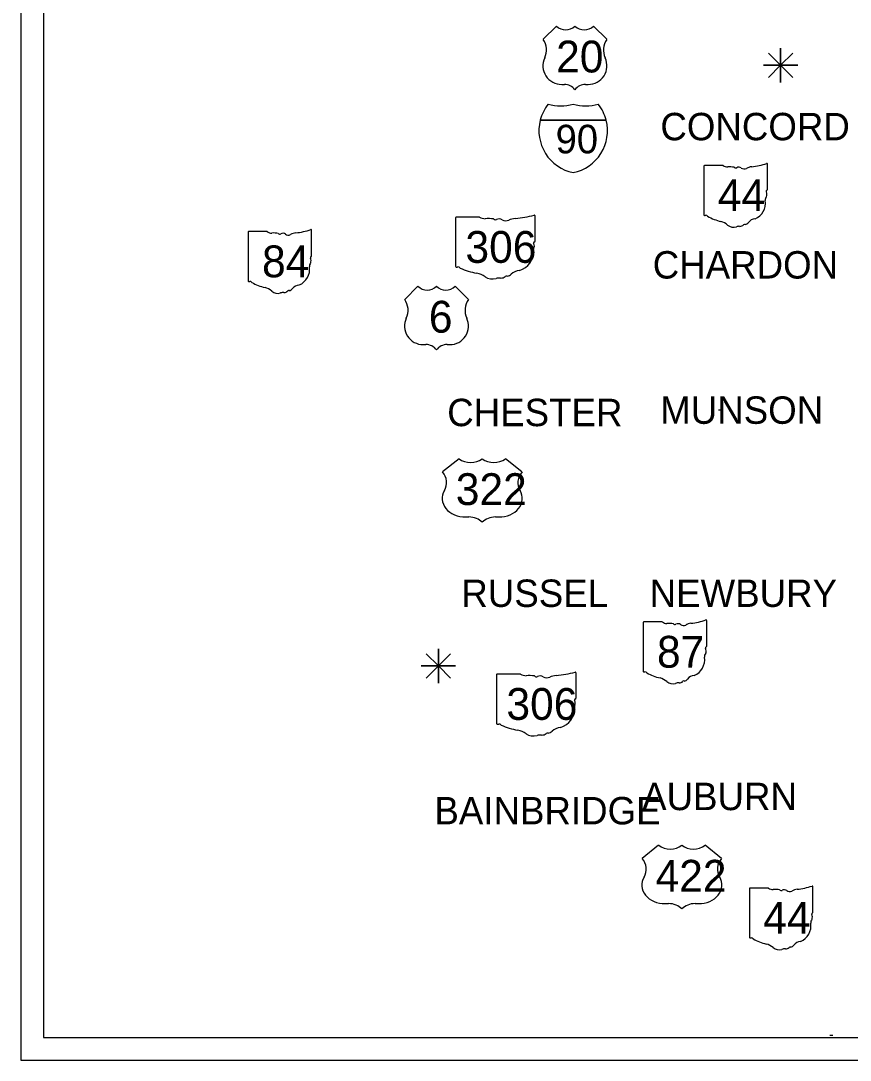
# Model space of a CAD drawing. Extents: x -1 to 48.3, y -9.3 to 22.
# Drawn here: x 2 to 5.63, y 14 to 18.55 of the extents above; entities that cross this region are included whole.
import ezdxf

# ---------------------------------------------------------------- set-up
doc = ezdxf.new("R2010")
doc.units = 0
for name, color, linetype in [('Default', 7, 'Continuous'), ('GM_X_County', 7, 'Continuous'), ('GM_X_County_Road', 7, 'Continuous'), ('GM_X_Minor_Lake_Text', 7, 'Continuous'), ('GM_X_Minor_River_Text', 7, 'Continuous'), ('GM_X_Township', 7, 'Continuous')]:
    doc.layers.add(name, color=color, linetype=linetype)

msp = doc.modelspace()

# ---------------------------------------------------------------- linework, layer by layer
at = {"layer": 'Default'}
for p, q in [((5.0538, 16.8468), (5.0668, 16.8468)), ((5.5402, 14.1091), (5.5532, 14.1091))]:
    msp.add_line(p, q, dxfattribs=at)
at = {"layer": 'GM_X_County'}
for p, q in [((2, 21), (2, 14)), ((2.1, 20.9), (2.1, 14.1)), ((2.1, 14.1), (8.9, 14.1)), ((2, 14), (9, 14))]:
    msp.add_line(p, q, dxfattribs=at)
at = {"layer": 'GM_X_County_Road'}
for p, q in [((4.9894, 17.913), (4.9894, 17.7017)), ((5.0737, 17.9167), (4.9921, 17.9167)), ((5.2678, 17.8114), (5.2678, 17.9219)), ((5.2678, 17.8114), (5.2678, 17.8114)), ((3.9026, 17.6867), (3.9026, 17.4754)), ((4.0079, 17.6903), (3.906, 17.6903)), ((4.2506, 17.585), (4.2506, 17.6956)), ((2.9944, 17.6237), (2.9944, 17.4123)), ((3.0787, 17.6273), (2.9971, 17.6273)), ((3.2728, 17.522), (3.2728, 17.6325)), ((4.2506, 17.5851), (4.2506, 17.585)), ((3.2728, 17.522), (3.2728, 17.522)), ((4.7233, 15.9147), (4.7233, 15.7033)), ((4.8076, 15.9183), (4.7261, 15.9183)), ((5.0018, 15.813), (5.0018, 15.9235)), ((5.0017, 15.813), (5.0018, 15.813)), ((4.0818, 15.6862), (4.0818, 15.4749)), ((4.1872, 15.6898), (4.0853, 15.6898)), ((4.4299, 15.5845), (4.4299, 15.6951)), ((4.4298, 15.5845), (4.4299, 15.5845)), ((5.1885, 14.7501), (5.1885, 14.5388)), ((5.2728, 14.7537), (5.1912, 14.7537)), ((5.4669, 14.6484), (5.4669, 14.759)), ((5.4669, 14.6484), (5.4669, 14.6484))]:
    msp.add_line(p, q, dxfattribs=at)
for centre, radius, start, end in [((4.9926, 17.9135), 0.00323, 98.1301, 188.1301), ((5.0931, 17.9412), 0.0313, 231.6195, 271.1119), ((5.1035, 17.798), 0.1123, 80.4867, 94.9883), ((5.129, 17.9146), 0.00903, 219.7921, 297.1024), ((5.1422, 17.8902), 0.0188, 54.4667, 119.1411), ((5.1664, 17.9237), 0.0226, 233.8562, 294.8282), ((5.2063, 17.8521), 0.0594, 97.3462, 120.7689), ((5.1687, 18.2048), 0.2953, 275.8445, 288.9065), ((5.2647, 17.9224), 0.0031, 351.8621, 97.738), ((5.2671, 17.8033), 0.0048, 107.944, 210.337), ((5.2366, 17.7893), 0.0288, 340.033, 23.6496), ((5.2645, 17.8109), 0.00332, 289.6038, 7.7341), ((5.1852, 17.751), 0.0739, 292.3089, 8.9858), ((5.2789, 17.7651), 0.021, 136.8065, 186.9296), ((4.9926, 17.7013), 0.00325, 171.9584, 258.3066), ((4.9931, 17.7229), 0.0248, 267.339, 280.6039), ((4.9982, 17.6895), 0.00895, 29.7484, 93.2717), ((5.1112, 17.8794), 0.2132, 240.4129, 257.1985), ((5.0477, 17.6068), 0.0667, 47.1842, 75.836), ((5.1198, 17.6885), 0.0423, 230.7004, 286.2918), ((5.1474, 17.6727), 0.0226, 268.777, 315.5493), ((5.1678, 17.6522), 0.00635, 65.7517, 132.6484), ((5.1651, 17.6812), 0.0239, 282.8732, 323.2771), ((5.2163, 17.6424), 0.0404, 94.4031, 142.5768), ((2.9976, 17.6241), 0.00323, 98.1301, 188.1301), ((3.0981, 17.6518), 0.0313, 231.6195, 271.1119), ((3.1085, 17.5087), 0.1123, 80.4867, 94.9883), ((3.134, 17.6252), 0.00903, 219.7921, 297.1024), ((3.1472, 17.6008), 0.0188, 54.4667, 119.1411), ((3.1714, 17.6343), 0.0226, 233.8562, 294.8282), ((3.2113, 17.5627), 0.0594, 97.3462, 120.7689), ((3.1737, 17.9154), 0.2953, 275.8445, 288.9065), ((3.2697, 17.633), 0.0031, 351.8621, 97.738), ((5.1443, 17.6154), 0.0348, 85.6951, 111.2099), ((3.2721, 17.5139), 0.0048, 107.944, 210.337), ((3.2695, 17.5216), 0.00332, 289.6038, 7.7341), ((3.1902, 17.4617), 0.0739, 292.3089, 8.9858), ((3.2839, 17.4757), 0.021, 136.8065, 186.9296), ((3.2416, 17.4999), 0.0288, 340.033, 23.6496), ((2.9976, 17.4119), 0.00325, 171.9584, 258.3066), ((2.9981, 17.4335), 0.0248, 267.339, 280.6039), ((3.0032, 17.4001), 0.00895, 29.7484, 93.2717), ((3.1163, 17.59), 0.2132, 240.4129, 257.1985), ((3.0527, 17.3174), 0.0667, 47.1842, 75.836), ((3.2213, 17.353), 0.0404, 94.4031, 142.5768), ((3.1248, 17.3991), 0.0423, 230.7004, 286.2918), ((3.1493, 17.326), 0.0348, 85.6951, 111.2099), ((3.1524, 17.3833), 0.0226, 268.777, 315.5493), ((3.1728, 17.3628), 0.00635, 65.7517, 132.6484), ((3.1701, 17.3918), 0.0239, 282.8732, 323.2771), ((4.9026, 16.2064), 0.2953, 275.8445, 288.9065), ((4.9987, 15.924), 0.0031, 351.8621, 97.738), ((4.7265, 15.9151), 0.00323, 98.1301, 188.1301), ((4.827, 15.9428), 0.0313, 231.6195, 271.1119), ((4.8374, 15.7996), 0.1123, 80.4867, 94.9883), ((4.8629, 15.9162), 0.00903, 219.7921, 297.1024), ((4.8762, 15.8918), 0.0188, 54.4667, 119.1411), ((4.9004, 15.9253), 0.0226, 233.8562, 294.8282), ((4.9402, 15.8537), 0.0594, 97.3462, 120.7689), ((5.001, 15.8049), 0.0048, 107.944, 210.337), ((4.9705, 15.7909), 0.0288, 340.033, 23.6496), ((4.9985, 15.8125), 0.00332, 289.6038, 7.7341), ((4.9191, 15.7527), 0.0739, 292.3089, 8.9858), ((5.0129, 15.7667), 0.021, 136.8065, 186.9296), ((4.7265, 15.7029), 0.00325, 171.9584, 258.3066), ((4.727, 15.7245), 0.0248, 267.339, 280.6039), ((4.7321, 15.6911), 0.00895, 29.7484, 93.2717), ((4.8452, 15.881), 0.2132, 240.4129, 257.1985), ((4.7816, 15.6084), 0.0667, 47.1842, 75.836), ((4.8538, 15.6901), 0.0423, 230.7004, 286.2918), ((4.8782, 15.617), 0.0348, 85.6951, 111.2099), ((4.8813, 15.6743), 0.0226, 268.777, 315.5493), ((4.9017, 15.6538), 0.00635, 65.7517, 132.6484), ((4.899, 15.6828), 0.0239, 282.8732, 323.2771), ((4.9503, 15.644), 0.0404, 94.4031, 142.5768), ((5.1917, 14.7505), 0.00323, 98.1301, 188.1301), ((5.2922, 14.7783), 0.0313, 231.6195, 271.1119), ((5.3026, 14.6351), 0.1123, 80.4867, 94.9883), ((5.3281, 14.7516), 0.00903, 219.7921, 297.1024), ((5.3413, 14.7272), 0.0188, 54.4667, 119.1411), ((5.3655, 14.7607), 0.0226, 233.8562, 294.8282), ((5.4054, 14.6892), 0.0594, 97.3462, 120.7689), ((5.3677, 15.0418), 0.2953, 275.8445, 288.9065), ((5.4638, 14.7594), 0.0031, 351.8621, 97.738), ((5.478, 14.6021), 0.021, 136.8065, 186.9296), ((5.4662, 14.6403), 0.0048, 107.944, 210.337), ((5.4357, 14.6263), 0.0288, 340.033, 23.6496), ((5.4636, 14.648), 0.00332, 289.6038, 7.7341), ((5.3843, 14.5881), 0.0739, 292.3089, 8.9858), ((5.1917, 14.5383), 0.00325, 171.9584, 258.3066), ((5.1922, 14.5599), 0.0248, 267.339, 280.6039), ((5.1973, 14.5266), 0.00895, 29.7484, 93.2717), ((5.3103, 14.7164), 0.2132, 240.4129, 257.1985), ((5.4154, 14.4794), 0.0404, 94.4031, 142.5768), ((5.2468, 14.4438), 0.0667, 47.1842, 75.836), ((5.3189, 14.5255), 0.0423, 230.7004, 286.2918), ((5.3434, 14.4525), 0.0348, 85.6951, 111.2099), ((5.3465, 14.5097), 0.0226, 268.777, 315.5493), ((5.3669, 14.4892), 0.00635, 65.7517, 132.6484), ((5.3642, 14.5183), 0.0239, 282.8732, 323.2771)]:
    msp.add_arc(centre, radius, start, end, dxfattribs=at)
for centre, major_axis, start_param, end_param in [((4.1266, 17.9784), (0.3691, 0), 4.814394, 5.042369), ((4.2467, 17.696), (0.00387, 0), 6.141152, 7.989035), ((3.9065, 17.6871), (0.00403, 0), 1.712693, 3.28349), ((4.0322, 17.7149), (0.0391, 0), 4.042523, 4.731795), ((4.0451, 17.5717), (0.1404, 0), 1.404758, 1.657858), ((4.077, 17.6882), (0.0113, 0), 3.836095, 5.185415), ((4.0936, 17.6638), (0.0235, 0), 0.950623, 2.079405), ((4.1239, 17.6973), (0.0282, 0), 4.081561, 5.145723), ((4.1737, 17.6258), (0.0743, 0), 1.699011, 2.107814), ((4.2497, 17.5769), (0.006, 0), 1.883978, 3.671073), ((4.2116, 17.5629), (0.036, 0), 5.934695, 6.695948), ((4.2465, 17.5846), (0.00415, 0), 5.05454, 6.418171), ((4.1473, 17.5247), (0.0923, 0), 5.101752, 6.440018), ((4.2645, 17.5388), (0.0262, 0), 2.387724, 3.262537), ((3.9066, 17.4749), (0.00407, 0), 3.00124, 4.508301), ((3.9072, 17.4965), (0.031, 0), 4.665946, 4.897461), ((3.9135, 17.4632), (0.0112, 0), 0.519207, 1.627899), ((4.0549, 17.653), (0.2665, 0), 4.195997, 4.488961), ((3.9754, 17.3804), (0.0834, 0), 0.823519, 1.323587), ((4.0656, 17.4621), (0.0529, 0), 4.026481, 4.996735), ((4.1, 17.4463), (0.0282, 0), 4.691044, 5.507374), ((4.1255, 17.4258), (0.00794, 0), 1.147584, 2.315152), ((4.1222, 17.4549), (0.0298, 0), 4.937069, 5.64225), ((4.1862, 17.416), (0.0506, 0), 1.647645, 2.488434), ((4.0962, 17.3891), (0.0435, 0), 1.495662, 1.94098), ((4.3059, 15.9779), (0.3691, 0), 4.814394, 5.042369), ((4.426, 15.6955), (0.00387, 0), 6.141152, 7.989035), ((4.0858, 15.6866), (0.00403, 0), 1.712693, 3.28349), ((4.2115, 15.7144), (0.0391, 0), 4.042523, 4.731795), ((4.2244, 15.5712), (0.1404, 0), 1.404758, 1.657858), ((4.2563, 15.6877), (0.0113, 0), 3.836095, 5.185415), ((4.2729, 15.6633), (0.0235, 0), 0.950623, 2.079405), ((4.3031, 15.6968), (0.0282, 0), 4.081561, 5.145723), ((4.353, 15.6253), (0.0743, 0), 1.699011, 2.107814), ((4.429, 15.5764), (0.006, 0), 1.883978, 3.671073), ((4.3908, 15.5624), (0.036, 0), 5.934695, 6.695948), ((4.4257, 15.5841), (0.00415, 0), 5.05454, 6.418171), ((4.3266, 15.5242), (0.0923, 0), 5.101752, 6.440018), ((4.4438, 15.5383), (0.0262, 0), 2.387724, 3.262537), ((4.0859, 15.4744), (0.00407, 0), 3.00124, 4.508301), ((4.0865, 15.496), (0.031, 0), 4.665946, 4.897461), ((4.0928, 15.4627), (0.0112, 0), 0.519207, 1.627899), ((4.2341, 15.6525), (0.2665, 0), 4.195997, 4.488961), ((4.1547, 15.3799), (0.0834, 0), 0.823519, 1.323587), ((4.2449, 15.4616), (0.0529, 0), 4.026481, 4.996735), ((4.2793, 15.4458), (0.0282, 0), 4.691044, 5.507374), ((4.3048, 15.4253), (0.00794, 0), 1.147584, 2.315152), ((4.3014, 15.4544), (0.0298, 0), 4.937069, 5.64225), ((4.3655, 15.4155), (0.0506, 0), 1.647645, 2.488434), ((4.2755, 15.3886), (0.0435, 0), 1.495662, 1.94098)]:
    msp.add_ellipse(centre, major_axis=major_axis, ratio=0.8, start_param=start_param, end_param=end_param, dxfattribs=at)
at = {"layer": 'GM_X_Minor_Lake_Text'}
for p, q in [((4.2733, 18.1149), (4.5619, 18.1149)), ((4.5619, 18.1149), (4.2733, 18.1149)), ((4.5619, 18.1149), (4.2733, 18.1149))]:
    msp.add_line(p, q, dxfattribs=at)
for centre, start, end in [((4.4551, 18.0689), 141.669, 165.8066), ((4.3628, 18.3645), 253.0091, 286.9909), ((4.4724, 18.3645), 253.0091, 286.9909), ((4.3801, 18.0689), 14.1934, 38.331), ((4.4551, 18.0689), 165.8066, 258.463), ((4.3801, 18.0689), 281.537, 14.1934)]:
    msp.add_arc(centre, 0.1875, start, end, dxfattribs=at)
at = {"layer": 'GM_X_Minor_River_Text'}
for p, q in [((4.344, 18.5267), (4.286, 18.4687)), ((4.5645, 18.4687), (4.5065, 18.5267)), ((4.3672, 18.2714), (4.3788, 18.2714)), ((4.4716, 18.2714), (4.4833, 18.2714)), ((3.7382, 17.3878), (3.6802, 17.3298)), ((3.9587, 17.3298), (3.9007, 17.3878)), ((3.7614, 17.1326), (3.773, 17.1326)), ((3.8659, 17.1326), (3.8775, 17.1326)), ((3.918, 16.6331), (3.8455, 16.5751)), ((4.1935, 16.5751), (4.121, 16.6331)), ((3.947, 16.3779), (3.9615, 16.3779)), ((4.0775, 16.3779), (4.092, 16.3779)), ((4.7916, 14.9408), (4.7191, 14.8828)), ((5.0672, 14.8828), (4.9947, 14.9408)), ((4.8207, 14.6855), (4.8352, 14.6855)), ((4.9512, 14.6855), (4.9657, 14.6855))]:
    msp.add_line(p, q, dxfattribs=at)
for centre, radius, start, end in [((4.3846, 18.5681), 0.058, 225.573, 314.427), ((4.4658, 18.5681), 0.058, 225.573, 314.427), ((4.2195, 18.4221), 0.0812, 334.5471, 35.0009), ((4.631, 18.4221), 0.0812, 144.9991, 205.4529), ((4.3663, 18.3527), 0.0812, 154.8319, 270.6383), ((4.4842, 18.3527), 0.0812, 269.3617, 25.1681), ((4.3788, 18.2134), 0.058, 36.8699, 90), ((4.4716, 18.2134), 0.058, 90, 143.1301), ((3.7788, 17.4292), 0.058, 225.573, 314.427), ((3.8601, 17.4292), 0.058, 225.573, 314.427), ((3.6137, 17.2832), 0.0812, 334.5471, 35.0009), ((4.0252, 17.2832), 0.0812, 144.9991, 205.4529), ((3.7605, 17.2138), 0.0812, 154.8319, 270.6383), ((3.8784, 17.2138), 0.0812, 269.3617, 25.1681), ((3.773, 17.0746), 0.058, 36.8699, 90), ((3.8659, 17.0746), 0.058, 90, 143.1301)]:
    msp.add_arc(centre, radius, start, end, dxfattribs=at)
for centre, major_axis, start_param, end_param in [((3.9687, 16.6745), (-0.0725, 0), 0.795399, 2.346194), ((4.0702, 16.6745), (-0.0725, 0), 0.795399, 2.346194), ((3.7623, 16.5285), (0.1015, 0), 5.838949, 6.894067), ((4.2767, 16.5285), (-0.1015, 0), 5.672304, 6.727422), ((3.9458, 16.4591), (0.1015, 0), 2.702327, 4.723529), ((4.0931, 16.4591), (-0.1015, 0), 1.559657, 3.580859), ((3.9615, 16.3198), (-0.0725, 0), 3.785094, 4.712389), ((4.0775, 16.3198), (-0.0725, 0), 4.712389, 5.639684), ((4.8424, 14.9822), (-0.0725, 0), 0.795399, 2.346194), ((4.9439, 14.9822), (-0.0725, 0), 0.795399, 2.346194), ((4.636, 14.8362), (0.1015, 0), 5.838949, 6.894067), ((5.1503, 14.8362), (-0.1015, 0), 5.672304, 6.727422), ((4.8195, 14.7667), (0.1015, 0), 2.702327, 4.723529), ((4.9668, 14.7667), (-0.1015, 0), 1.559657, 3.580859), ((4.8352, 14.6275), (-0.0725, 0), 3.785094, 4.712389), ((4.9512, 14.6275), (-0.0725, 0), 4.712389, 5.639684)]:
    msp.add_ellipse(centre, major_axis=major_axis, ratio=0.8, start_param=start_param, end_param=end_param, dxfattribs=at)
at = {"layer": 'GM_X_Township'}
for points in [[(5.2505, 18.3552), (5.3255, 18.3552), (5.2725, 18.4083), (5.3255, 18.3552), (5.3255, 18.4302), (5.3255, 18.3552), (5.3786, 18.4083), (5.3255, 18.3552), (5.4005, 18.3552), (5.3255, 18.3552), (5.3786, 18.3022), (5.3255, 18.3552), (5.3255, 18.2802), (5.3255, 18.3552), (5.2725, 18.3022), (5.3255, 18.3552)], [(3.7526, 15.7256), (3.8276, 15.7256), (3.7745, 15.7786), (3.8276, 15.7256), (3.8276, 15.8006), (3.8276, 15.7256), (3.8806, 15.7786), (3.8276, 15.7256), (3.9026, 15.7256), (3.8276, 15.7256), (3.8806, 15.6726), (3.8276, 15.7256), (3.8276, 15.6506), (3.8276, 15.7256), (3.7745, 15.6726), (3.8276, 15.7256)]]:
    msp.add_lwpolyline(points, close=True, dxfattribs=at)

# ---------------------------------------------------------------- texts
at = {"layer": 'GM_X_County_Road'}
for s, p in [('44', (5.0504, 17.7166)), ('306', (3.946, 17.4903)), ('84', (3.0558, 17.4272)), ('87', (4.7843, 15.7182)), ('306', (4.1253, 15.4898)), ('44', (5.2494, 14.5537))]:
    msp.add_text(s, height=0.13922, dxfattribs=at).set_placement(p)
at = {"layer": 'GM_X_Minor_Lake_Text'}
msp.add_text('90', height=0.125, dxfattribs=at).set_placement((4.3406, 17.9696))
at = {"layer": 'GM_X_Minor_River_Text'}
for s, height, p in [('20', 0.13922, (4.3429, 18.3237)), ('6', 0.1392, (3.7858, 17.1848)), ('322', 0.13922, (3.9038, 16.4301)), ('422', 0.13922, (4.7779, 14.7377))]:
    msp.add_text(s, height=height, dxfattribs=at).set_placement(p)
at = {"layer": 'GM_X_Township'}
for s, p in [('CONCORD', (4.7992, 18.0268)), ('CHARDON', (4.7656, 17.4216)), ('CHESTER', (3.8662, 16.7754)), ('MUNSON', (4.7984, 16.7857)), ('RUSSEL', (3.9281, 15.9841)), ('NEWBURY', (4.7521, 15.9841)), ('AUBURN', (4.7193, 15.0946)), ('BAINBRIDGE', (3.8102, 15.0323))]:
    msp.add_text(s, height=0.12, rotation=0, dxfattribs=at).set_placement(p)

doc.saveas('drawing.dxf')
